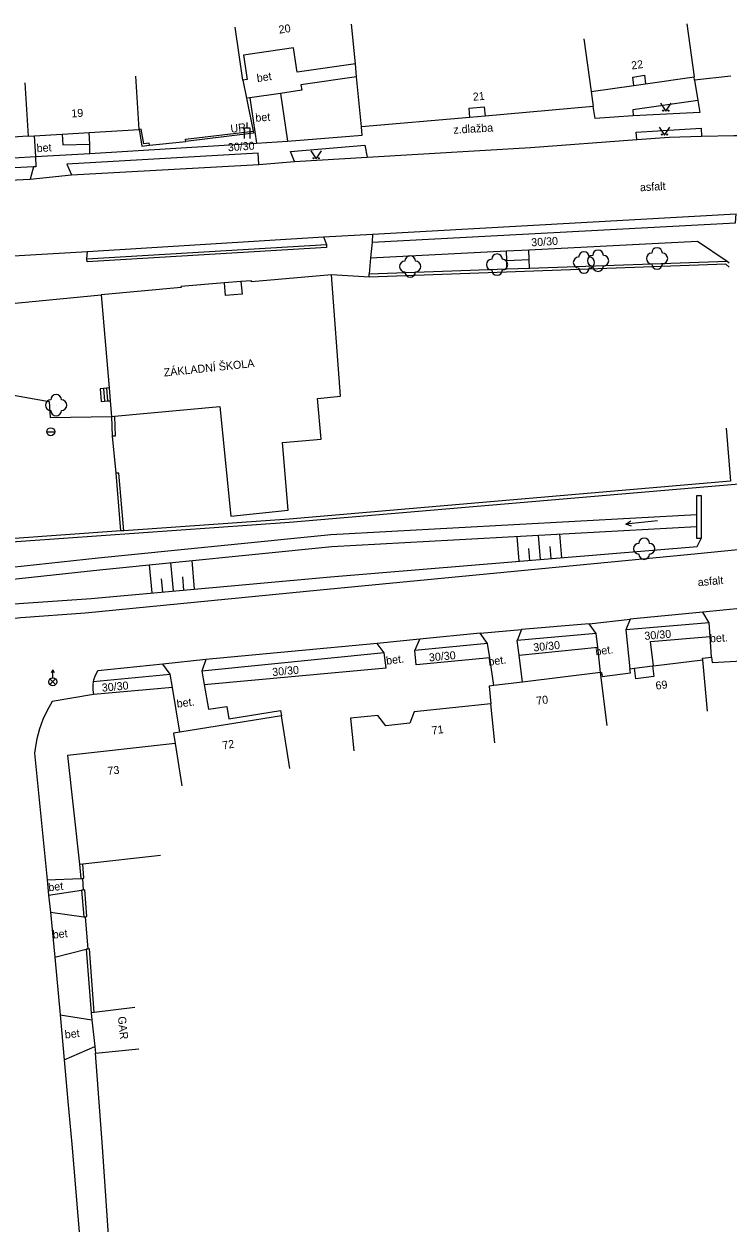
# Model space of a CAD drawing. Extents: x -544674 to -541478, y -1199076 to -1195527.
# Drawn here: x -541789 to -541723, y -1198842.7 to -1198730.4 of the extents above; entities that cross this region are included whole.
import ezdxf

# ---------------------------------------------------------------- set-up
doc = ezdxf.new("R2010")
doc.units = 0
for name, color, linetype in [('BUDOVY_MĚŘ', 7, 'Continuous'), ('POMOC_POPIS', 7, 'Continuous'), ('ROZHRANÍ_PLOCH', 7, 'Continuous'), ('VÝŠKOPIS', 7, 'Continuous'), ('ZELEŇ', 7, 'Continuous'), ('ZN_BP', 7, 'Continuous'), ('ZN_DOPLŇKOVÉ', 7, 'Continuous'), ('ZN_KULTUR', 7, 'Continuous'), ('Č_POPIS_ORIENT', 7, 'Continuous')]:
    doc.layers.add(name, color=color, linetype=linetype)

msp = doc.modelspace()

# ---------------------------------------------------------------- linework, layer by layer
at = {"layer": 'BUDOVY_MĚŘ'}
for points in [[(-541768.51, -1198735.6), (-541769.23, -1198730.65)], [(-541757.97, -1198734.07), (-541758.32, -1198730.38)], [(-541726.92, -1198730.35), (-541726.21, -1198735.3)], [(-541736.57, -1198731.73), (-541735.86, -1198736.68)], [(-541757.97, -1198734.07), (-541763.43, -1198734.86), (-541763.76, -1198732.59), (-541768.44, -1198733.27), (-541768.11, -1198735.54), (-541768.51, -1198735.6)], [(-541757.85, -1198735.3), (-541757.97, -1198734.07)], [(-541778.24, -1198740.23), (-541778.54, -1198735.24)], [(-541757.4, -1198739.99), (-541757.85, -1198735.3)], [(-541731.87, -1198736.11), (-541731.98, -1198735.32), (-541730.88, -1198735.16), (-541730.77, -1198735.95)], [(-541730.77, -1198735.95), (-541726.21, -1198735.3)], [(-541726.18, -1198735.6), (-541726.21, -1198735.3)], [(-541722.79, -1198735.24), (-541726.18, -1198735.6)], [(-541788.95, -1198735.87), (-541788.65, -1198740.86)], [(-541735.86, -1198736.68), (-541731.87, -1198736.11)], [(-541735.86, -1198736.68), (-541735.69, -1198738.09)], [(-541731.87, -1198736.11), (-541730.77, -1198735.95)], [(-541747.23, -1198739.1), (-541747.3, -1198738.25), (-541745.89, -1198738.12), (-541745.81, -1198738.98)], [(-541745.81, -1198738.98), (-541747.23, -1198739.1)], [(-541735.69, -1198738.09), (-541745.81, -1198738.98)], [(-541747.23, -1198739.1), (-541757.4, -1198739.99)], [(-541788.65, -1198740.86), (-541788.06, -1198740.82)], [(-541788.06, -1198740.82), (-541785.45, -1198740.67)], [(-541785.45, -1198740.67), (-541782.93, -1198740.52)], [(-541785.45, -1198740.67), (-541785.39, -1198741.69), (-541782.86, -1198741.6)], [(-541782.93, -1198740.52), (-541778.24, -1198740.23)], [(-541782.86, -1198741.6), (-541782.93, -1198740.52)], [(-541770.24, -1198754.62), (-541774.32, -1198754.95), (-541774.31, -1198755.05), (-541781.8, -1198755.74)], [(-541780.54, -1198767.09), (-541770.68, -1198766.2), (-541769.63, -1198776.46), (-541764.27, -1198775.91), (-541764.79, -1198769.57), (-541761.18, -1198769.24), (-541761.53, -1198765.43), (-541759.37, -1198765.23), (-541760.21, -1198753.85)], [(-541768.69, -1198754.49), (-541768.59, -1198755.66), (-541770.15, -1198755.78), (-541770.24, -1198754.62)], [(-541768.69, -1198754.49), (-541770.24, -1198754.62)], [(-541760.21, -1198753.85), (-541767.69, -1198754.51), (-541767.7, -1198754.41), (-541768.69, -1198754.49)], [(-541781.8, -1198755.74), (-541781.06, -1198764.46)], [(-541781.06, -1198764.46), (-541780.96, -1198765.65)], [(-541780.96, -1198765.65), (-541780.84, -1198767.12)], [(-541780.84, -1198767.12), (-541780.54, -1198767.09)], [(-541724.58, -1198789.69), (-541724.53, -1198790.19), (-541721.72, -1198790.02), (-541721.74, -1198789.52)], [(-541735, -1198791.12), (-541734.9, -1198791.11), (-541734.85, -1198791.5), (-541732.2, -1198791.16), (-541732.25, -1198790.76)], [(-541732.25, -1198790.76), (-541731.82, -1198790.71)], [(-541730.12, -1198790.5), (-541729.99, -1198791.49), (-541731.7, -1198791.7), (-541731.82, -1198790.71)], [(-541731.82, -1198790.71), (-541730.12, -1198790.5)], [(-541730.12, -1198790.5), (-541730.03, -1198790.49)], [(-541730.03, -1198790.49), (-541725.42, -1198789.92)], [(-541725.42, -1198789.92), (-541725.43, -1198789.77), (-541724.58, -1198789.69)], [(-541724.96, -1198794.75), (-541725.42, -1198789.92)], [(-541735, -1198791.12), (-541742.31, -1198792.01)], [(-541734.36, -1198796.08), (-541735, -1198791.12)], [(-541744.99, -1198792.34), (-541745.44, -1198792.4), (-541745.28, -1198794.07)], [(-541742.31, -1198792.01), (-541744.99, -1198792.34)], [(-541745.28, -1198794.07), (-541752.45, -1198794.82), (-541752.86, -1198795.87), (-541755.11, -1198796.12), (-541755.85, -1198795.15), (-541758.42, -1198795.4), (-541758.12, -1198798.46)], [(-541744.9, -1198797.72), (-541745.28, -1198794.07)], [(-541764.9, -1198795.17), (-541774.43, -1198796.71)], [(-541764.1, -1198800.11), (-541764.9, -1198795.17)], [(-541774.43, -1198796.71), (-541775.02, -1198796.81), (-541774.87, -1198797.77)], [(-541774.87, -1198797.77), (-541784.94, -1198798.9), (-541783.81, -1198809.09)], [(-541774.87, -1198797.77), (-541774.23, -1198801.74)], [(-541783.51, -1198809.06), (-541776.24, -1198808.25)], [(-541783.81, -1198809.09), (-541783.51, -1198809.06)], [(-541782.44, -1198822.97), (-541782.74, -1198823)], [(-541782.74, -1198823), (-541782.66, -1198823.68)], [(-541778.63, -1198822.52), (-541782.44, -1198822.97)], [(-541782.66, -1198823.68), (-541782.4, -1198826.17)], [(-541782.4, -1198826.17), (-541782.33, -1198826.8)], [(-541782.33, -1198826.8), (-541778.27, -1198826.37)]]:
    msp.add_lwpolyline(points, dxfattribs=at)
at = {"layer": 'ROZHRANÍ_PLOCH'}
for points in [[(-541757.85, -1198735.3), (-541763.07, -1198736.06), (-541763, -1198736.56), (-541764.98, -1198736.85)], [(-541726.18, -1198735.6), (-541725.87, -1198737.51)], [(-541767.85, -1198737.26), (-541768.17, -1198737.31)], [(-541764.98, -1198736.85), (-541767.85, -1198737.26)], [(-541767.85, -1198737.26), (-541767.23, -1198741.52)], [(-541764.98, -1198736.85), (-541764.33, -1198741.33)], [(-541725.87, -1198737.51), (-541731.97, -1198738.38), (-541731.94, -1198738.96)], [(-541725.87, -1198737.51), (-541725.68, -1198738.66), (-541731.94, -1198738.96)], [(-541731.94, -1198738.96), (-541735.49, -1198739.2), (-541735.69, -1198738.09)], [(-541764.33, -1198741.33), (-541757.33, -1198740.78), (-541757.4, -1198739.99)], [(-541731.58, -1198741.17), (-541731.65, -1198740.48), (-541725.57, -1198740.12), (-541725.52, -1198740.85)], [(-541788.06, -1198740.82), (-541787.96, -1198742.78)], [(-541767.23, -1198741.52), (-541764.33, -1198741.33)], [(-541756.88, -1198742.83), (-541741.56, -1198741.93), (-541731.58, -1198741.17)], [(-541731.58, -1198741.17), (-541728.56, -1198740.97), (-541725.52, -1198740.85)], [(-541725.52, -1198740.85), (-541722.49, -1198740.81), (-541722.23, -1198740.81)], [(-541767.02, -1198743.51), (-541767.09, -1198742.44), (-541785, -1198743.5), (-541784.57, -1198744.5)], [(-541782.86, -1198742.48), (-541767.23, -1198741.52)], [(-541782.86, -1198742.48), (-541782.86, -1198741.6)], [(-541763.69, -1198743.25), (-541764.06, -1198742.29), (-541757.08, -1198741.71), (-541756.88, -1198742.83)], [(-541806.25, -1198743.88), (-541787.96, -1198742.78)], [(-541787.96, -1198742.78), (-541787.91, -1198743.73), (-541788.15, -1198743.74)], [(-541787.96, -1198742.78), (-541782.86, -1198742.48)], [(-541784.57, -1198744.5), (-541767.02, -1198743.51)], [(-541767.02, -1198743.51), (-541763.69, -1198743.25)], [(-541763.69, -1198743.25), (-541756.88, -1198742.83)], [(-541788.15, -1198743.74), (-541795.83, -1198744.13)], [(-541788.15, -1198743.74), (-541788.46, -1198744.89)], [(-541788.46, -1198744.89), (-541784.57, -1198744.5)], [(-541795.56, -1198745.22), (-541788.46, -1198744.89)], [(-541756.41, -1198750.78), (-541722.33, -1198748.97), (-541722.28, -1198748.13)], [(-541756.37, -1198750.03), (-541722.28, -1198748.13)], [(-541783.08, -1198751.66), (-541760.95, -1198750.28)], [(-541760.95, -1198750.28), (-541756.37, -1198750.03)], [(-541760.95, -1198750.28), (-541760.69, -1198751)], [(-541756.37, -1198750.03), (-541756.41, -1198750.78)], [(-541756.41, -1198750.78), (-541756.55, -1198752.27)], [(-541741.7, -1198751.51), (-541725.92, -1198750.71), (-541723.14, -1198752.56)], [(-541844.79, -1198755.59), (-541813.27, -1198753.45), (-541794.31, -1198752.32), (-541783.08, -1198751.66)], [(-541783.13, -1198752.35), (-541783.08, -1198751.66)], [(-541756.55, -1198752.27), (-541756.69, -1198753.77)], [(-541756.55, -1198752.27), (-541743.82, -1198751.62)], [(-541743.82, -1198751.62), (-541741.7, -1198751.51)], [(-541743.79, -1198752.52), (-541743.82, -1198751.62)], [(-541743.79, -1198752.52), (-541741.67, -1198752.41)], [(-541743.76, -1198753.3), (-541743.79, -1198752.52)], [(-541741.67, -1198752.41), (-541741.7, -1198751.51)], [(-541741.64, -1198753.22), (-541741.67, -1198752.41)], [(-541756.68, -1198754.07), (-541760.21, -1198753.85)], [(-541803.12, -1198757.8), (-541781.8, -1198755.74)], [(-541802.17, -1198767.94), (-541797.43, -1198767.58), (-541797.4, -1198766.58), (-541793.42, -1198765.18), (-541791.22, -1198764.9), (-541786.68, -1198765.73), (-541786.58, -1198767.24), (-541780.84, -1198767.12)], [(-541781.59, -1198764.5), (-541781.89, -1198764.53), (-541781.79, -1198765.72), (-541781.49, -1198765.69)], [(-541781.29, -1198764.48), (-541781.59, -1198764.5)], [(-541781.59, -1198764.5), (-541781.49, -1198765.69)], [(-541781.06, -1198764.46), (-541781.29, -1198764.48)], [(-541781.29, -1198764.48), (-541781.19, -1198765.67)], [(-541781.49, -1198765.69), (-541781.19, -1198765.67)], [(-541781.19, -1198765.67), (-541780.96, -1198765.65)], [(-541710.2, -1198778.44), (-541725.87, -1198780), (-541761.28, -1198783.4), (-541783.3, -1198785.55), (-541789.31, -1198786.01), (-541799.01, -1198787.05)], [(-541721.6, -1198785.1), (-541725.41, -1198785.46)], [(-541736.07, -1198786.57), (-541732.23, -1198786.12)], [(-541732.23, -1198786.12), (-541732.62, -1198787.13)], [(-541725.41, -1198785.46), (-541732.23, -1198786.12)], [(-541724.82, -1198786.47), (-541725.41, -1198785.46)], [(-541746.27, -1198787.42), (-541742.4, -1198787.09)], [(-541742.4, -1198787.09), (-541742.8, -1198788.13)], [(-541736.07, -1198786.57), (-541742.4, -1198787.09)], [(-541735.39, -1198787.47), (-541736.07, -1198786.57)], [(-541724.82, -1198786.47), (-541732.62, -1198787.13)], [(-541732.62, -1198787.13), (-541732.25, -1198790.76)], [(-541724.73, -1198787.74), (-541724.82, -1198786.47)], [(-541755.92, -1198788.39), (-541771.98, -1198789.91)], [(-541751.93, -1198787.99), (-541755.92, -1198788.39)], [(-541755.26, -1198789.29), (-541755.92, -1198788.39)], [(-541752.39, -1198789.05), (-541751.93, -1198787.99)], [(-541745.59, -1198788.41), (-541752.39, -1198789.05)], [(-541746.27, -1198787.42), (-541751.93, -1198787.99)], [(-541745.59, -1198788.41), (-541746.27, -1198787.42)], [(-541745.38, -1198789.76), (-541745.59, -1198788.41)], [(-541735.39, -1198787.47), (-541742.8, -1198788.13)], [(-541742.63, -1198789.49), (-541742.8, -1198788.13)], [(-541735.25, -1198788.76), (-541735.39, -1198787.47)], [(-541730.03, -1198790.49), (-541730.31, -1198788.22), (-541724.73, -1198787.74)], [(-541724.58, -1198789.69), (-541724.73, -1198787.74)], [(-541755.26, -1198789.29), (-541772.36, -1198790.98)], [(-541772.14, -1198792.25), (-541755.09, -1198790.67), (-541755.26, -1198789.29)], [(-541745.38, -1198789.76), (-541752.26, -1198790.4), (-541752.39, -1198789.05)], [(-541742.63, -1198789.49), (-541735.25, -1198788.76)], [(-541742.31, -1198792.01), (-541742.63, -1198789.49)], [(-541735, -1198791.12), (-541735.25, -1198788.76)], [(-541776.02, -1198790.33), (-541782.11, -1198790.95), (-541782.15, -1198791), (-541782.37, -1198791.4), (-541782.52, -1198791.83), (-541782.54, -1198791.97)], [(-541771.98, -1198789.91), (-541776.02, -1198790.33)], [(-541775.33, -1198791.27), (-541776.02, -1198790.33)], [(-541771.98, -1198789.91), (-541772.36, -1198790.98)], [(-541744.99, -1198792.34), (-541745.38, -1198789.76)], [(-541782.54, -1198791.97), (-541775.33, -1198791.27)], [(-541775.12, -1198792.52), (-541775.33, -1198791.27)], [(-541772.36, -1198790.98), (-541772.14, -1198792.25)], [(-541782.54, -1198791.97), (-541782.59, -1198792.28), (-541782.59, -1198792.74), (-541782.5, -1198793.19)], [(-541775.12, -1198792.52), (-541782.5, -1198793.19)], [(-541774.43, -1198796.71), (-541775.12, -1198792.52)], [(-541772.14, -1198792.25), (-541771.74, -1198794.55), (-541770.02, -1198794.31), (-541769.83, -1198795.46), (-541764.98, -1198794.68), (-541764.9, -1198795.17)], [(-541782.5, -1198793.19), (-541786.39, -1198793.85), (-541786.86, -1198794.67), (-541787.25, -1198795.52), (-541787.58, -1198796.41), (-541787.82, -1198797.32), (-541787.99, -1198798.24), (-541788.04, -1198798.68), (-541786.87, -1198810.56)], [(-541786.87, -1198810.56), (-541783.71, -1198810.42)], [(-541786.87, -1198810.56), (-541786.72, -1198811.98)], [(-541786.72, -1198811.98), (-541783.64, -1198811.51)], [(-541786.72, -1198811.98), (-541786.55, -1198813.58)], [(-541786.55, -1198813.58), (-541786.14, -1198817.78)], [(-541786.55, -1198813.58), (-541783.43, -1198814.01)], [(-541786.14, -1198817.78), (-541783.19, -1198817.04)], [(-541786.14, -1198817.78), (-541785.64, -1198823.21)], [(-541785.64, -1198823.21), (-541785.27, -1198827.4)], [(-541785.64, -1198823.21), (-541782.66, -1198823.68)], [(-541785.27, -1198827.4), (-541782.4, -1198826.17)], [(-541785.27, -1198827.4), (-541784.92, -1198831.32), (-541784.54, -1198835.33), (-541783.86, -1198843.52), (-541783.27, -1198851.72), (-541782.75, -1198859.92), (-541782.31, -1198868.13), (-541782.05, -1198873.86), (-541781.41, -1198891.95), (-541780.84, -1198910.05), (-541780.69, -1198915.38), (-541780.25, -1198927.91), (-541779.95, -1198938.23), (-541779.87, -1198939.2), (-541779.74, -1198940.04)]]:
    msp.add_lwpolyline(points, dxfattribs=at)
at = {"layer": 'VÝŠKOPIS'}
for points in [[(-541742.61, -1198780.7), (-541742.8, -1198778.36)], [(-541740.61, -1198780.54), (-541740.8, -1198778.25)], [(-541738.62, -1198780.37), (-541738.8, -1198778.14)], [(-541741.61, -1198780.62), (-541741.7, -1198779.49)], [(-541739.62, -1198780.45), (-541739.71, -1198779.32)], [(-541773.04, -1198783.31), (-541773.28, -1198780.63)], [(-541777.03, -1198783.66), (-541777.26, -1198781.02)], [(-541775.03, -1198783.48), (-541775.27, -1198780.82)], [(-541776.03, -1198783.57), (-541776.14, -1198782.33)], [(-541774.04, -1198783.4), (-541774.15, -1198782.15)]]:
    msp.add_lwpolyline(points, dxfattribs=at)
at = {"layer": 'ZELEŇ'}
for centre in [(-541735.23, -1198752.53), (-541729.7, -1198752.32), (-541752.84, -1198753.08), (-541744.69, -1198752.9), (-541736.55, -1198752.7), (-541786.02, -1198766.07), (-541730.9, -1198779.52)]:
    msp.add_circle(centre, 0.0005, dxfattribs=at)
for centre, start, end in [((-541729.7, -1198751.82), 0, 179.99999), ((-541752.84, -1198752.58), 0, 179.99999), ((-541745.19, -1198752.9), 89.99999, 269.99999), ((-541744.69, -1198752.4), 0, 179.99999), ((-541744.19, -1198752.9), 270, 89.99999), ((-541737.05, -1198752.7), 89.99999, 269.99999), ((-541736.55, -1198752.2), 0, 179.99999), ((-541735.73, -1198752.53), 89.99999, 269.99999), ((-541736.05, -1198752.7), 270, 89.99999), ((-541735.23, -1198752.03), 0, 179.99999), ((-541734.73, -1198752.53), 270, 89.99999), ((-541730.2, -1198752.32), 89.99999, 269.99999), ((-541729.2, -1198752.32), 270, 89.99999), ((-541753.34, -1198753.08), 89.99999, 269.99999), ((-541752.84, -1198753.58), 179.99999, 359.99999), ((-541752.34, -1198753.08), 270, 89.99999), ((-541744.69, -1198753.4), 179.99999, 359.99999), ((-541736.55, -1198753.2), 179.99999, 359.99999), ((-541735.23, -1198753.03), 179.99999, 359.99999), ((-541729.7, -1198752.82), 179.99999, 359.99999), ((-541786.52, -1198766.07), 89.99999, 269.99999), ((-541786.02, -1198765.57), 0, 179.99999), ((-541785.52, -1198766.07), 270, 89.99999), ((-541786.02, -1198766.57), 179.99999, 359.99999), ((-541731.4, -1198779.52), 89.99999, 269.99999), ((-541730.9, -1198779.02), 0, 179.99999), ((-541730.4, -1198779.52), 270, 89.99999), ((-541730.9, -1198780.02), 179.99999, 359.99999)]:
    msp.add_arc(centre, 0.5, start, end, dxfattribs=at)
at = {"layer": 'ZN_BP'}
for p, q in [((-541786.595, -1198792.254), (-541786.066, -1198791.726)), ((-541786.066, -1198792.258), (-541786.595, -1198791.726)), ((-541786.33, -1198791.615), (-541786.33, -1198790.865))]:
    msp.add_line(p, q, dxfattribs=at)
msp.add_lwpolyline([(-541786.455, -1198791.115), (-541786.33, -1198790.865), (-541786.205, -1198791.115)], dxfattribs=at)
msp.add_circle((-541786.33, -1198791.99), 0.375, dxfattribs=at)
at = {"layer": 'ZN_DOPLŇKOVÉ'}
for p, q in [((-541768.1, -1198740.09), (-541768.1, -1198739.59)), ((-541786.895, -1198768.56), (-541786.145, -1198768.56))]:
    msp.add_line(p, q, dxfattribs=at)
for points in [[(-541768.51, -1198735.6), (-541768.17, -1198737.31)], [(-541768.17, -1198737.31), (-541767.55, -1198740.39)], [(-541777.28, -1198741.72), (-541777.31, -1198741.52), (-541777.81, -1198741.58), (-541778.04, -1198740.2), (-541778.24, -1198740.23)], [(-541768.35, -1198741.09), (-541768.35, -1198740.09), (-541767.85, -1198740.09), (-541767.85, -1198741.09)], [(-541788.65, -1198740.86), (-541798.84, -1198741.53)], [(-541778.24, -1198740.23), (-541777.98, -1198741.8), (-541777.28, -1198741.72)], [(-541773.87, -1198741.35), (-541773.89, -1198741.15), (-541767.55, -1198740.39)], [(-541767.55, -1198740.39), (-541767.53, -1198740.59), (-541773.87, -1198741.35)], [(-541777.28, -1198741.72), (-541773.87, -1198741.35)], [(-541783.13, -1198752.35), (-541760.69, -1198751)], [(-541760.67, -1198751.3), (-541783.11, -1198752.65), (-541783.13, -1198752.35)], [(-541760.69, -1198751), (-541760.67, -1198751.3)], [(-541741.64, -1198753.22), (-541723.14, -1198752.56)], [(-541723.14, -1198752.56), (-541722.95, -1198752.74)], [(-541756.69, -1198753.77), (-541743.76, -1198753.3)], [(-541722.95, -1198753.15), (-541723.25, -1198752.86), (-541756.68, -1198754.07)], [(-541743.76, -1198753.3), (-541741.64, -1198753.22)], [(-541756.68, -1198754.07), (-541756.69, -1198753.77)], [(-541799.49, -1198779.54), (-541764.13, -1198777.04), (-541722.38, -1198773.46), (-541708.23, -1198772.31), (-541706.34, -1198755.86)], [(-541780.84, -1198767.12), (-541780.77, -1198768.98)], [(-541780.54, -1198767.09), (-541780.47, -1198768.97), (-541780.77, -1198768.98)], [(-541723.21, -1198768.21), (-541722.81, -1198773.19), (-541743.48, -1198774.97), (-541764.16, -1198776.74), (-541779.67, -1198777.83)], [(-541780.77, -1198768.98), (-541780.43, -1198772.45)], [(-541779.67, -1198777.83), (-541780.13, -1198772.43), (-541780.43, -1198772.45)], [(-541780.43, -1198772.45), (-541779.97, -1198777.85)], [(-541725.96, -1198778.56), (-541725.97, -1198774.54), (-541725.57, -1198774.54), (-541725.56, -1198778.56), (-541725.96, -1198778.56)], [(-541798.28, -1198782.12), (-541782.07, -1198780.37), (-541760.26, -1198778.19), (-541725.97, -1198776.3)], [(-541779.97, -1198777.85), (-541780.35, -1198777.88), (-541799.51, -1198779.25), (-541799.49, -1198779.54)], [(-541798.21, -1198783.25), (-541781.95, -1198781.49), (-541760.17, -1198779.32), (-541725.96, -1198777.43)], [(-541779.67, -1198777.83), (-541779.97, -1198777.85)], [(-541798.13, -1198785.24), (-541782.72, -1198784.17), (-541760.3, -1198782.17), (-541725.93, -1198779.32), (-541725.56, -1198778.56)], [(-541783.81, -1198809.09), (-541783.71, -1198810.42)], [(-541783.56, -1198810.41), (-541783.41, -1198810.4), (-541783.51, -1198809.06)], [(-541783.71, -1198810.42), (-541783.56, -1198810.41)], [(-541783.56, -1198810.41), (-541783.49, -1198811.5)], [(-541783.49, -1198811.5), (-541783.64, -1198811.51)], [(-541783.64, -1198811.51), (-541783.43, -1198814.01)], [(-541783.28, -1198814), (-541783.13, -1198813.99), (-541783.34, -1198811.49), (-541783.49, -1198811.5)], [(-541783.43, -1198814.01), (-541783.28, -1198814)], [(-541783.28, -1198814), (-541783.04, -1198817.03)], [(-541783.04, -1198817.03), (-541783.19, -1198817.04)], [(-541783.19, -1198817.04), (-541782.74, -1198823)], [(-541782.44, -1198822.97), (-541782.89, -1198817.02), (-541783.04, -1198817.03)], [(-541780.35, -1198856.29), (-541780.86, -1198847.53), (-541781.67, -1198835.58), (-541782.33, -1198826.8)]]:
    msp.add_lwpolyline(points, dxfattribs=at)
msp.add_circle((-541786.52, -1198768.56), 0.375, dxfattribs=at)
at = {"layer": 'ZN_KULTUR'}
msp.add_line((-541729.639, -1198776.899), (-541732.621, -1198777.221), dxfattribs=at)
for points in [[(-541729.38, -1198737.77), (-541728.88, -1198738.52), (-541728.38, -1198737.77)], [(-541729.5, -1198740.01), (-541729, -1198740.76), (-541728.5, -1198740.01)], [(-541762.15, -1198742.23), (-541761.65, -1198742.98), (-541761.15, -1198742.23)], [(-541732.097, -1198777.416), (-541732.621, -1198777.221), (-541732.151, -1198776.919)]]:
    msp.add_lwpolyline(points, dxfattribs=at)
for centre in [(-541729.13, -1198738.47), (-541728.63, -1198738.47), (-541729.25, -1198740.71), (-541728.75, -1198740.71), (-541761.9, -1198742.93), (-541761.4, -1198742.93)]:
    msp.add_circle(centre, 0.05, dxfattribs=at)

# ---------------------------------------------------------------- texts
at = {"layer": 'POMOC_POPIS'}
for s, rotation, p in [('bet', 8.25002, (-541767.16, -1198735.8)), ('bet', 3.75001, (-541767.32, -1198739.51)), ('UR', 6.84003, (-541769.63, -1198740.55)), ('z.dlažba', 3.36, (-541748.77, -1198740.64)), ('bet', 3.82999, (-541787.82, -1198742.37)), ('30/30', 3.69002, (-541769.9, -1198742.28)), ('asfalt', 3.19, (-541731.28, -1198746.03)), ('30/30', 3.37002, (-541741.47, -1198751.19)), ('ZÁKLADNÍ ŠKOLA', 6.06, (-541775.89, -1198763.39)), ('asfalt', 5.33, (-541725.85, -1198783.04)), ('30/30', 4.91002, (-541730.85, -1198788.07)), ('30/30', 5.64002, (-541741.26, -1198789.15)), ('bet.', 3.43001, (-541724.72, -1198788.3)), ('bet.', 7.46003, (-541755.04, -1198790.39)), ('30/30', 5.33, (-541751.04, -1198790.09)), ('bet.', 7.46003, (-541745.46, -1198790.49)), ('bet.', 7.46003, (-541735.43, -1198789.53)), ('30/30', 5.33, (-541765.73, -1198791.46)), ('30/30', 5.16, (-541781.7, -1198792.92)), ('bet.', 7.46003, (-541774.67, -1198794.42)), ('bet', 6.04001, (-541786.71, -1198811.63)), ('bet', 6.04001, (-541786.3, -1198816.06)), ('GAR', 276.04001, (-541780.23, -1198823.38)), ('bet', 6.04001, (-541785.17, -1198825.42))]:
    msp.add_text(s, height=0.75, rotation=rotation, dxfattribs=at).set_placement(p)
at = {"layer": 'Č_POPIS_ORIENT'}
for s, rotation, p in [('20', 8.25999, (-541765.1, -1198731.26)), ('22', 8.12998, (-541732.06, -1198734.62)), ('21', 5.08002, (-541746.93, -1198737.55)), ('19', 3.45998, (-541784.57, -1198739.11)), ('69', 7.01002, (-541729.79, -1198792.73)), ('70', 7.26997, (-541740.97, -1198794.15)), ('71', 7.09998, (-541750.77, -1198796.93)), ('72', 9.17999, (-541770.37, -1198798.33)), ('73', 6.19001, (-541781.16, -1198800.72))]:
    msp.add_text(s, height=0.75, rotation=rotation, dxfattribs=at).set_placement(p)

doc.saveas('drawing.dxf')
